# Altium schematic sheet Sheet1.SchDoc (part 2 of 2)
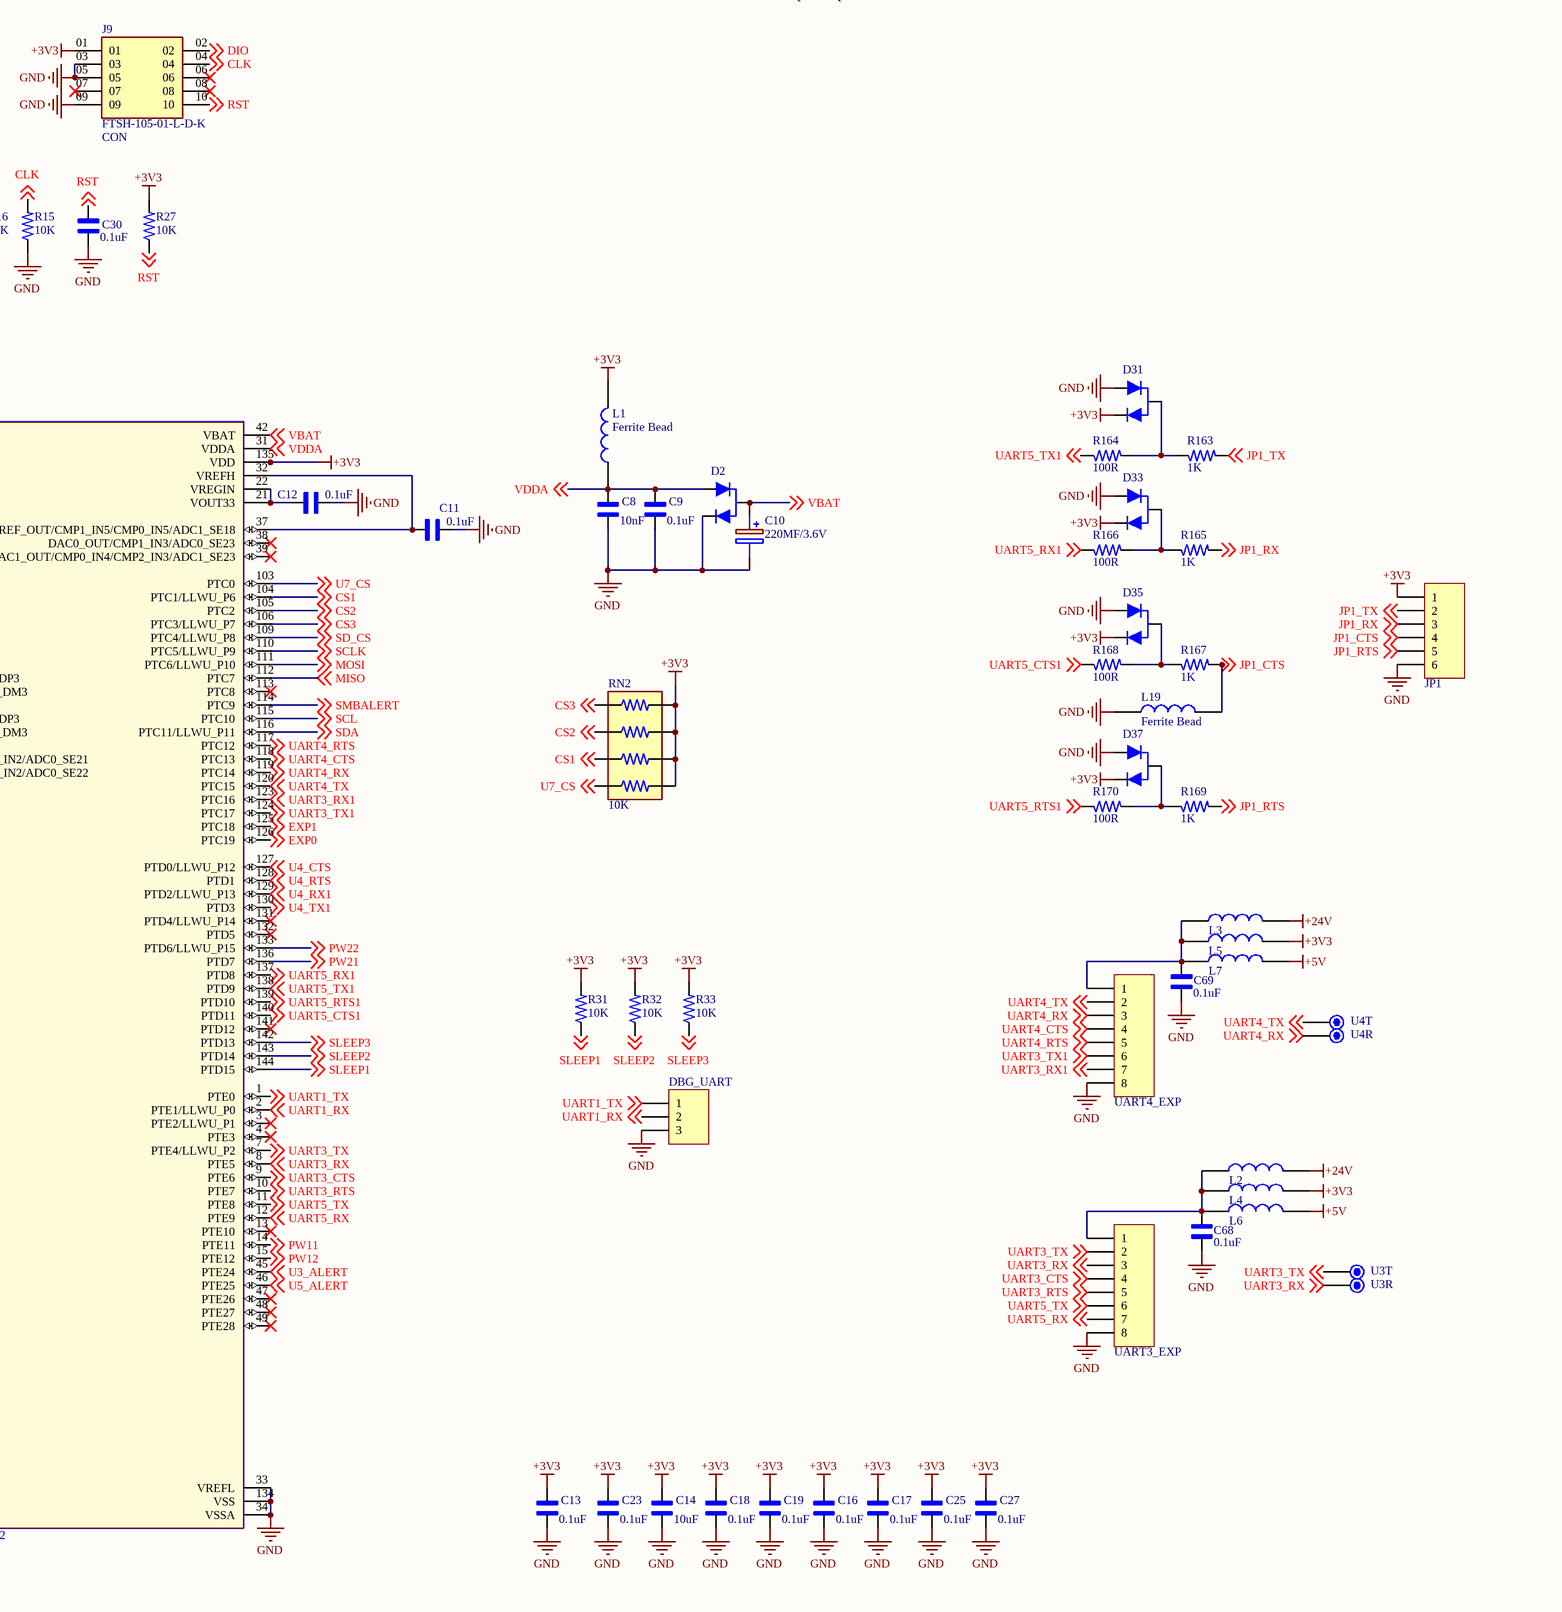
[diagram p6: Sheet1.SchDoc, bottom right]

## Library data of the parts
3V3_IN 5V_IN BUZ P1 P2 = 68000-102HLF: Header, 2-Pin, 2.54mm, male; MF: Amphenol ICC (FCI); Value: 2 pin CON
C3-C8 C15 C70-C77 C104 C111 C154 = 08055C103KAT2A: CAP CER 10000PF 50V X7R 0805; MF: AVX Corporation
C9 C11-C13 C16-C19 C23 C25 C27-C30 C33 C35 C37 C41-C43 C48-C50 C61 C63 C68 C69 C86 C101 C108 C114 C123 C124 C136 C139-C145 C147 C149 C153 C155 = 0805B104K500CT: 0.1µF ±10% 50V Ceramic Capacitor X7R 0805 (2012 Metric); MF: Walsin Technology Corporation
C10 = EEC-RG0V224H: CAP 220MF -20% +80% 3.6V T/H; MF: Panasonic Electronic Components
C14 C34 C105 C125 = GRM21BR61E106KA73L: CAP CER 10UF 25V X5R 0805; MF: Murata Electronics
C20 C24 = 0805N180J500CT: Multilayer Ceramic Capacitors MLCC - SMD/SMT 18pF +-5% 50V; MF: Walsin
C21 C22 = 0805N120J500CT: Multilayer Ceramic Capacitors MLCC - SMD/SMT 12pF +-5% 50V; MF: Walsin
C38-C40 C106 C109 C110 C126-C135 C146 C148 = GRM32ER71H106KA12L: CAP CER 10UF 50V X7R 1210; MF: Murata Electronics
C44-C47 C51-C55 C121 = 08055C105KAT2A: CAP CER 1UF 50V X7R 0805; MF: AVX Corporation
C56-C59 C115 C118 = 08055C102KAT4A: CAP CER 1000PF 50V X7R 0805; MF: AVX Corporation
C60 C62 C64-C67 = ESH477M050AH4AA: CAP ALUM 470UF 20% 50V THRU HOLE; MF: KEMET
C107 = VJ0805A101JXAAC: CAP CER 100PF 50V C0G/NP0 0805; MF: Vishay Vitramon
C112 = UMK212B7224KG-T: CAP CER 0.22UF 50V X7R 0805; MF: Taiyo Yuden
C113 C150 = GRM21BR60J226ME39L: CAP CER 22UF 6.3V X5R 0805; MF: Murata Electronics
C116 = CC0805ZRY5V9BB474: CAP CER 0.47UF 50V Y5V 0805; MF: Yageo
C117 C122 = VJ0805V334MXACW1BC: CAP CER 0.33UF 50V Y5V 0805; MF: Vishay Vitramon
C119 = C1206C104M5RACTU: CAP CER 0.1UF 50V X7R 1206; MF: KEMET
C120 = UMK212BB7225KG-T: CAP CER 2.2UF 50V X7R 0805; MF: Taiyo Yuden
C137 = 860020675017: CAP ALUM 120UF 20% 50V RADIAL; MF: Würth Elektronik
C138 = 1206X226K160CT: Multilayer Ceramic Capacitors MLCC - SMD/SMT 1206 MLCC X5R 22 uF +/ -10% 16 V T&R GP; MF: Walsin
D2 = BAS40-04E6327: BAS40 - HIGH SPEED SWITCHING, CL; MF: Infineon Technologies
D3-D6 D15-D22 D31 D33 D35 D37 = BAT54S,215: DIODE ARRAY SCHOTTKY 30V SOT23; MF: Nexperia USA Inc.
D7 D8 D23-D26 = BAS40-06: SCHOTTKY SOT-23 40V 0.2A; MF: Diotec Semiconductor
D9-D14 = SMLJ43CA: TVS DIODE 43V 69.4V SMC; MF: Bourns Inc.
D27 D29 D40 = BZX384-B15,115: DIODE ZENER 15V 300MW SOD323; MF: Nexperia USA Inc.
D28 D32 = SMAJ43A-E3/61: TVS DIODE 43V 69.4V DO214AC; MF: Vishay General Semiconductor - Diodes Division
D30 D36 D38 = 1N4148WS-7-F: Diode Standard 75V 150mA Surface Mount SOD-323; MF: Diodes Incorporated
D34 D39 = MBRD20100CT-13: DIODE SCHOTTKY 100V 10A TO252; MF: Diodes Incorporated
DBG_UART = 68000-103HLF: Header, 3-Pin, 2.54mm, male; MF: Amphenol ICC (FCI); Value: 3pin CON
ENC_1 ENC_2 JP4 = 68000-104HLF: Connector Header Through Hole 4 position 0.100" (2.54mm); MF: Amphenol ICC (FCI); Value: 4pin CON
F1 F2 = C3130: 5x20 Fuse Holders RoHS; MF: Xucheng Elec
GPIO_EXP UART3_EXP UART4_EXP = 68001-108HLF: Header, 8-Pin, 2.54mm, male; MF: Amphenol ICC (FCI)
IC1 = LMV321IDBVR: General Purpose Amplifier Circuit Rail-to-Rail SOT-23-5; MF: Texas Instruments
IC3-IC9 = BSC360N15NS3 G: MOSFET N-Ch 150V 33A TDSON-8 OptiMOS 3; MF: Infineon Technologies
J2 J8 J10-J12 J14-J20 J22-J24 J26 J27 = 62409-1: Faston 20-16 AWG Straight Non-Insulated Printed Circuit Board Tab Terminal   Pitch  0.250 SOLDER; MF: TE Connectivity AMP Connectors
J9 = FTSH-105-01-L-D-K: Connector Header Through Hole 10 position 0.050" (1.27mm); MF: Samtec
J28 = DM3AT-SF-PEJM5: 10 (8 + 2) Position Card Connector Secure Digital - microSD™ Surface Mount, Right Angle Gold; MF: Hirose
JP1 = 68000-106HLF: Connector Header Through Hole 6 position 0.100" (2.54mm); MF: Amphenol ICC (FCI)
JP2 = 68000-105HLF: Connector Header Through Hole 5 position 0.100" (2.54mm); MF: Amphenol ICC (FCI); Value: 5pin CON
JP3 JP5-JP7 = PH1-01-UA: Connector Header Through Hole 1 position 0.100" (2.54mm); MF: Adam Tech
K1 = HFE20-1/5-1HST-L2(257): HFE20 Series 5 V 5 mm Pin 1 FORM A Sealed Miniature Dual Coil Latching Relay; MF: Hongfa
L1-L7 L17 L19 = BK2125HS601-T: - Ferrite Bead 0805 (2012 Metric) 500mA 300mOhm; MF: Taiyo Yuden
L10 = XAL1010-103MEB: Fixed Inductors 10uH Shld 20% 15.5A 14.75mOhms AECQ2; MF: COILCRAFT
L12 L13 = SRN6045-150M: FIXED IND 15UH 1.9A 95.8MOHM SMD; MF: Bourns Inc.
LED1-LED5 LED7-LED10 LED13-LED15 = EL-17-21SURC/S530-A2/TR8: Standard LEDs - SMD Red Water Clear 624nm 42mcd; MF: Everlight
PW11 PW12 PW21 PW22 PW31 PW32 U2R1 U2T1 U3R U3T U4R U4T V_BRIDGE V_BUT = E_PAD(SMD)
Q1 = CRGCQ0603F390K
Q2-Q7 = PDTC114ET,215: TRANS PREBIAS NPN 250MW TO236AB; MF: Nexperia USA Inc.
Q8 Q10 Q14 = BC847B-7-F: TRANS NPN 45V 0.1A SOT23-3; MF: Diodes Incorporated
Q9 = SI7611DN-T1-GE3: MOSFET P-CH 40V 18A PPAK1212-8; MF: Vishay Siliconix
Q13 Q15-Q17 = BD140: Bipolar _BJT_ Transistor PNP 80V 1.5A 1.25W Through Hole SOT-32-3
R4 R25 R26 R37 R38 R42-R47 R52-R54 R57 R58 R63 R64 R66-R70 R71#1 R71#2 R72 R75-R82 R84 R85 R88 R102 R107-R116 R118 R119 R122 R127 R143-R145 R147-R156 R159 R160 R179 R181 R182 R184 R187 = RC0805FR-070RL: RES SMD 0 OHM JUMPER 1/8W 0805; MF: Yageo
R5-R10 R13 R28 R30 R83 R95 R132 R136 R163 R165 R167 R169 R171 R177 R183 R185 R186 R188 = RC0805FR-071KL: RES SMD 1K OHM 1% 1/8W 0805; MF: Yageo
R11 R12 R23 R24 R34-R36 R39-R41 R176 = CRCW08054K70FKEA: RES SMD 4.7K OHM 1% 1/8W 0805; MF: Vishay Dale
R15-R22 R27 R31-R33 R56 R60 R62 R65 R73 R106 R123 R125 R128 R131 R135 = RC0805FR-0710KL: 10 kOhms ±1% 0.125W, 1/8W Chip Resistor 0805 (2012 Metric) Moisture Resistant Thick Film; MF: Yageo
R48-R51 R164 R166 R168 R170 = WR08X1000FTL: RES 100 OHM 1% 1/8W 0805; MF: Walsin Technology Corporation
R55 R59 R61 = CSR2512A0R01F: RES 0.01 OHM 1% 2W 2512; MF: Riedon
R96 R146 = CRCW080510M0FKEA: RES SMD 10M OHM 1% 1/8W 0805; MF: Vishay Dale
R97 = RC0805FR-0751KL: RES SMD 51K OHM 1% 1/8W 0805; MF: Yageo
R99 R129 R137 R173 = RC0805FR-0733KL: RES SMD 33K OHM 1% 1/8W 0805; MF: Yageo
R100 R134 = RC0805FR-0722K1L: RES SMD 22.1K OHM 1% 1/8W 0805; MF: Yageo
R103 = RC0805FR-07226KL: RES SMD 226K OHM 1% 1/8W 0805; MF: Yageo
R104 R105 = RC0805FR-0764K9L: RES SMD 64.9K OHM 1% 1/8W 0805; MF: Yageo
R117 = RC0805FR-07200RL: RES SMD 200 OHM 1% 1/8W 0805; MF: Yageo
R120 = RT0805BRD07301KL: RES SMD 301K OHM 0.1% 1/8W 0805; MF: Yageo
R121 = RC0805FR-0795K3L: RES SMD 95.3K OHM 1% 1/8W 0805; MF: Yageo
R124 R130 = PA2512FKF7W0R004E: RES 0.004 OHM 1% 2W 2512; MF: Yageo
R126 R138 = RC1206FR-0710RL: RES SMD 10 OHM 1% 1/4W 1206; MF: Yageo
R133 R172 R174 = RC0805FR-0788K7L: RES SMD 88.7K OHM 1% 1/8W 0805; MF: Yageo
R139 R141 R142 R178 R? = CRCW0805100KFKEA: RES SMD 100K OHM 1% 1/8W 0805; MF: Vishay Dale
R157 R158 R161 R162 = CRCW0805470RFKEAC: RES 470 OHM 1% 1/8W 0805; MF: Vishay Dale
R175 = RC0805JR-0743KL: RES SMD 43K OHM 5% 1/8W 0805; MF: Yageo
R180 = ERJ-6ENF2204V: RES SMD 2.2M OHM 1% 1/8W 0805; MF: Panasonic Electronic Components
RN1 RN3 = TC164-JR-0747RL: 47 Ohm ±5% 62.5mW Power Per Element Isolated 4 Resistor Network/Array ±200ppm/°C 1206 (3216 Metric), Concave, Long Side Terminals; MF: Yageo
RN2 = TC164-JR-0710KL: RES ARRAY 4 RES 10K OHM 1206; MF: Yageo
SJ1 SJ2 = JUMP_3: 3 (1 x 3) Position Shunt Connector Black Open Top
U3 U5 = TMP75AIDR: SENSOR DIGITAL -40C-125C 8SOIC; MF: Texas Instruments
U4 = MK22FN1M0AVLQ12: ARMÂ® CortexÂ®-M4 Kinetis K20 Microcontroller IC 32-Bit 120MHz 1MB _1M x 8_ FLASH 144-LQFP _20x20_; MF: NXP USA
U7 = TMP75AIDR: SENSOR; MF: Texas Instruments
U8 = XB3-24Z8UM-J: 802.15.4 ZigbeeÂ® Transceiver Module 2.4GHz Antenna Not Included, U.FL Surface Mount; MF: Digi International
U9-U11 = DRV8703QRHBTQ1: Automotive 45-V H-bridge smart gate driver with SPI control 32-VQFN -40 to 125; MF: Texas Instruments
U12-U23 = JMTK50N06A: MOSFET DIP JMTK50N06A N-ch 60V 50A TO-252,Jie Jie Micro; Value: MOSFET-N
U27 U33 = TPS560430XFDBVT: IC REG BUCK PWM 600MA SOT23-6; MF: Texas Instruments
U29 = LTC4015EUHF#PBF: Charger IC Multi-Chemistry 38-QFN (5x7); MF: Analog Devices
U35 = TL431ACDBZR: Shunt Voltage Reference IC 36V Â±1% SOT-23-3; MF: Texas Instruments
Y1 = ABM3B-8.000MHZ-B2-T: 8MHz Â±20ppm Crystal 18pF 200 Ohms 4-SMD, No Lead; MF: Abracon LLC
Y2 = ABS07-32.768KHZ-T: CRYSTAL 32.7680KHZ 12.5PF 2-SMD; MF: Abracon LLC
